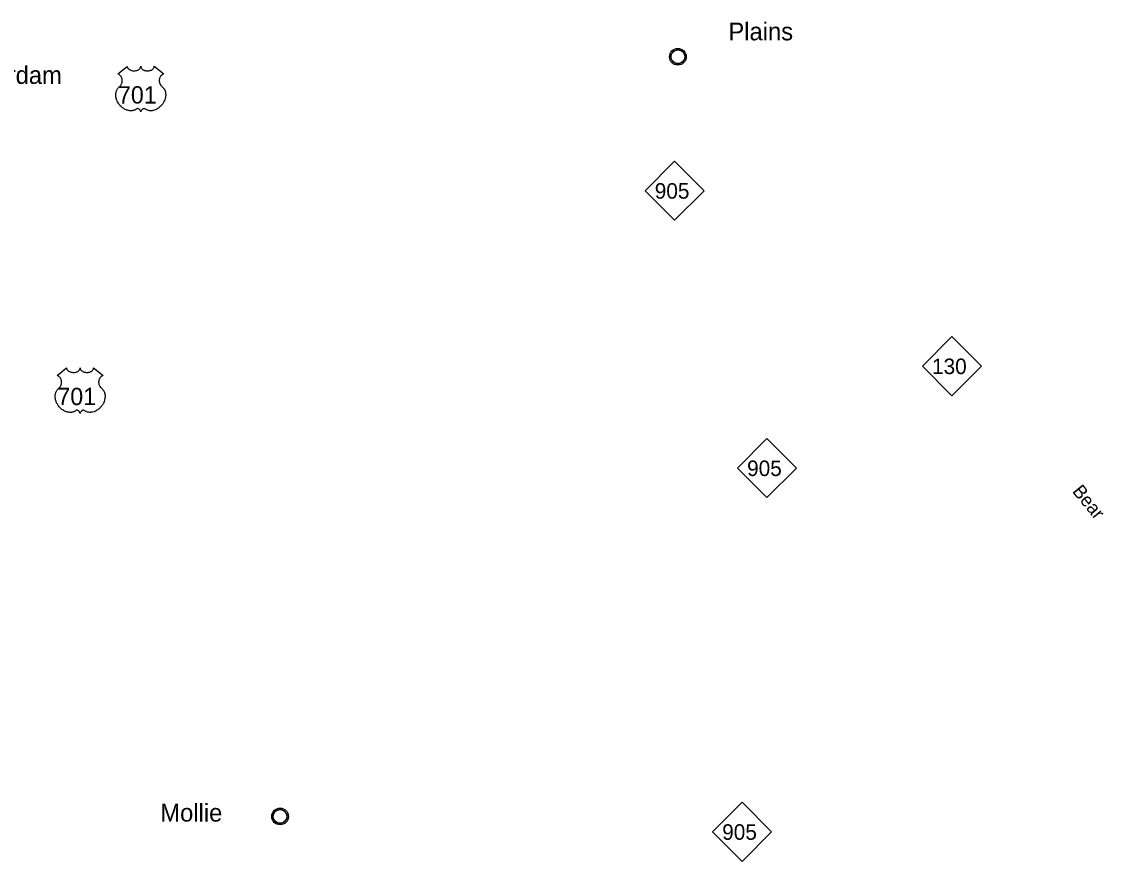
# Model space of a CAD drawing. Extents: x 5197761 to 5514561, y 1890130 to 2080942.
# Drawn here: x 5297901 to 5346637, y 1945242 to 1983085 of the extents above; entities that cross this region are included whole.
import ezdxf

# ---------------------------------------------------------------- set-up
doc = ezdxf.new("R2010")
doc.units = 0
for name, color, linetype in [('Exist Civil Demographics Community CELL', 7, 'Continuous'), ('Exist Civil Demographics Community Label', 7, 'Continuous'), ('Exist Hydrographic Creek Single Shore Label', 7, 'Continuous'), ('Exist Road Primary NC Shield CELL', 7, 'Continuous'), ('Exist Road Primary NC Shield Number Label', 7, 'Continuous'), ('Exist Road Primary US Shield CELL', 7, 'Continuous'), ('Exist Road Primary US Shield Number Label', 7, 'Continuous')]:
    doc.layers.add(name, color=color, linetype=linetype)

msp = doc.modelspace()

# ---------------------------------------------------------------- linework, layer by layer
at = {"layer": 'Exist Civil Demographics Community CELL'}
for points in [[(5327158, 1981552), (5327162, 1981574), (5327169, 1981600), (5327180, 1981629), (5327192, 1981652), (5327205, 1981675), (5327220, 1981695), (5327236, 1981713), (5327255, 1981731), (5327277, 1981750), (5327299, 1981764), (5327318, 1981776), (5327338, 1981786), (5327360, 1981795), (5327383, 1981802), (5327400, 1981807), (5327419, 1981810), (5327436, 1981813), (5327461, 1981814), (5327479, 1981813), (5327502, 1981812), (5327521, 1981809), (5327541, 1981805), (5327561, 1981800), (5327582, 1981792), (5327608, 1981780), (5327633, 1981766), (5327654, 1981752), (5327674, 1981736), (5327687, 1981723), (5327704, 1981706), (5327719, 1981687), (5327732, 1981669), (5327744, 1981649), (5327754, 1981628), (5327762, 1981608), (5327768, 1981588), (5327774, 1981570), (5327778, 1981545), (5327780, 1981527), (5327781, 1981503), (5327781, 1981479), (5327778, 1981457), (5327775, 1981435), (5327768, 1981410), (5327761, 1981387), (5327751, 1981366), (5327739, 1981342), (5327726, 1981321), (5327712, 1981302), (5327695, 1981283), (5327674, 1981264), (5327654, 1981247), (5327634, 1981233), (5327616, 1981223), (5327589, 1981210), (5327561, 1981200), (5327537, 1981194), (5327510, 1981188), (5327493, 1981187), (5327475, 1981186), (5327452, 1981186), (5327435, 1981187), (5327413, 1981190), (5327389, 1981195), (5327371, 1981201), (5327350, 1981208), (5327332, 1981216), (5327316, 1981225), (5327289, 1981241), (5327266, 1981258), (5327247, 1981276), (5327229, 1981296), (5327216, 1981312), (5327204, 1981328), (5327188, 1981357), (5327181, 1981371), (5327174, 1981387), (5327164, 1981420), (5327158, 1981448), (5327155, 1981469), (5327154, 1981494), (5327153, 1981513), (5327156, 1981538)], [(5309233, 1947316), (5309237, 1947338), (5309244, 1947364), (5309256, 1947393), (5309267, 1947416), (5309281, 1947439), (5309296, 1947459), (5309312, 1947477), (5309330, 1947495), (5309352, 1947514), (5309374, 1947528), (5309393, 1947540), (5309414, 1947550), (5309436, 1947559), (5309458, 1947566), (5309475, 1947571), (5309495, 1947574), (5309511, 1947577), (5309537, 1947578), (5309554, 1947577), (5309577, 1947576), (5309597, 1947573), (5309616, 1947569), (5309636, 1947564), (5309657, 1947556), (5309684, 1947544), (5309709, 1947530), (5309729, 1947516), (5309750, 1947500), (5309763, 1947487), (5309779, 1947470), (5309795, 1947451), (5309807, 1947433), (5309820, 1947413), (5309829, 1947392), (5309838, 1947372), (5309844, 1947352), (5309849, 1947334), (5309853, 1947309), (5309856, 1947291), (5309857, 1947267), (5309856, 1947243), (5309854, 1947221), (5309850, 1947199), (5309844, 1947174), (5309836, 1947151), (5309827, 1947131), (5309814, 1947107), (5309801, 1947085), (5309787, 1947066), (5309770, 1947047), (5309749, 1947028), (5309729, 1947011), (5309709, 1946997), (5309692, 1946987), (5309665, 1946974), (5309636, 1946964), (5309612, 1946958), (5309586, 1946953), (5309568, 1946951), (5309550, 1946950), (5309528, 1946950), (5309511, 1946951), (5309488, 1946954), (5309464, 1946959), (5309446, 1946965), (5309425, 1946972), (5309407, 1946980), (5309391, 1946989), (5309364, 1947005), (5309342, 1947022), (5309322, 1947040), (5309304, 1947060), (5309292, 1947076), (5309280, 1947092), (5309263, 1947121), (5309256, 1947135), (5309250, 1947151), (5309239, 1947184), (5309233, 1947212), (5309230, 1947233), (5309229, 1947258), (5309229, 1947277), (5309231, 1947303)]]:
    msp.add_lwpolyline(points, close=True, dxfattribs=at)
for centre, radius in [((5327468, 1981502), 377), ((5327467, 1981503), 307), ((5309544, 1947266), 377), ((5309542, 1947267), 307)]:
    msp.add_circle(centre, radius, dxfattribs=at)
at = {"layer": 'Exist Road Primary NC Shield CELL'}
for points in [[(5325990, 1975466), (5327322, 1976798), (5328654, 1975466), (5327322, 1974134)], [(5338481, 1967560), (5339813, 1968892), (5341145, 1967560), (5339813, 1966228)], [(5330150, 1962966), (5331482, 1964298), (5332814, 1962966), (5331482, 1961634)], [(5329028, 1946574), (5330360, 1947906), (5331692, 1946574), (5330360, 1945242)]]:
    msp.add_lwpolyline(points, close=True, dxfattribs=at)
at = {"layer": 'Exist Road Primary US Shield CELL'}
for points in [[(5302659, 1981070), (5302660, 1981053), (5302664, 1981032), (5302667, 1981021), (5302677, 1981000), (5302693, 1980976), (5302716, 1980952), (5302741, 1980931), (5302758, 1980920), (5302787, 1980905), (5302820, 1980891), (5302857, 1980880), (5302894, 1980873), (5302935, 1980868), (5302975, 1980867), (5303019, 1980871), (5303067, 1980880), (5303090, 1980886), (5303114, 1980894), (5303137, 1980904), (5303163, 1980917), (5303183, 1980931), (5303199, 1980942), (5303222, 1980964), (5303240, 1980986), (5303247, 1980999), (5303254, 1981011), (5303263, 1981036), (5303265, 1981048), (5303267, 1981071), (5303268, 1981051), (5303270, 1981039), (5303274, 1981027), (5303279, 1981014), (5303288, 1980996), (5303298, 1980981), (5303317, 1980959), (5303329, 1980948), (5303339, 1980939), (5303368, 1980919), (5303402, 1980902), (5303419, 1980895), (5303436, 1980889), (5303457, 1980882), (5303480, 1980877), (5303502, 1980873), (5303524, 1980870), (5303547, 1980868), (5303566, 1980867), (5303589, 1980868), (5303611, 1980869), (5303632, 1980872), (5303657, 1980876), (5303676, 1980880), (5303701, 1980887), (5303725, 1980895), (5303745, 1980904), (5303771, 1980917), (5303793, 1980931), (5303808, 1980943), (5303827, 1980960), (5303844, 1980981), (5303855, 1980996), (5303862, 1981011), (5303869, 1981027), (5303873, 1981044), (5303875, 1981059), (5303875, 1981072), (5304300, 1980733), (5304290, 1980729), (5304267, 1980718), (5304249, 1980707), (5304220, 1980686), (5304207, 1980675), (5304195, 1980663), (5304183, 1980651), (5304173, 1980639), (5304161, 1980622), (5304150, 1980605), (5304139, 1980586), (5304131, 1980570), (5304118, 1980535), (5304111, 1980514), (5304107, 1980495), (5304102, 1980458), (5304101, 1980439), (5304101, 1980422), (5304102, 1980403), (5304104, 1980385), (5304107, 1980366), (5304110, 1980349), (5304116, 1980329), (5304123, 1980305), (5304132, 1980282), (5304152, 1980246), (5304177, 1980208), (5304195, 1980187), (5304212, 1980169), (5304238, 1980147), (5304253, 1980134), (5304269, 1980118), (5304296, 1980087), (5304306, 1980072), (5304317, 1980056), (5304327, 1980039), (5304337, 1980021), (5304345, 1980005), (5304360, 1979969), (5304371, 1979933), (5304376, 1979915), (5304384, 1979873), (5304387, 1979852), (5304390, 1979812), (5304391, 1979762), (5304387, 1979716), (5304378, 1979661), (5304371, 1979629), (5304360, 1979591), (5304349, 1979558), (5304329, 1979509), (5304312, 1979474), (5304290, 1979433), (5304274, 1979408), (5304257, 1979381), (5304234, 1979351), (5304208, 1979318), (5304177, 1979284), (5304151, 1979258), (5304118, 1979229), (5304098, 1979212), (5304070, 1979191), (5304030, 1979164), (5303992, 1979142), (5303959, 1979125), (5303930, 1979113), (5303892, 1979098), (5303829, 1979081), (5303806, 1979076), (5303779, 1979072), (5303754, 1979070), (5303729, 1979068), (5303696, 1979068), (5303663, 1979071), (5303632, 1979075), (5303600, 1979082), (5303566, 1979092), (5303535, 1979104), (5303504, 1979119), (5303451, 1979153), (5303436, 1979161), (5303428, 1979163), (5303407, 1979164), (5303388, 1979160), (5303369, 1979152), (5303357, 1979146), (5303341, 1979135), (5303329, 1979126), (5303315, 1979112), (5303305, 1979101), (5303297, 1979092), (5303282, 1979068), (5303277, 1979057), (5303271, 1979043), (5303266, 1979022), (5303260, 1979048), (5303252, 1979066), (5303243, 1979081), (5303234, 1979094), (5303219, 1979111), (5303205, 1979124), (5303189, 1979137), (5303172, 1979148), (5303159, 1979155), (5303146, 1979159), (5303131, 1979163), (5303118, 1979164), (5303108, 1979164), (5303094, 1979161), (5303074, 1979147), (5303056, 1979134), (5303036, 1979122), (5303013, 1979109), (5302996, 1979101), (5302975, 1979093), (5302951, 1979085), (5302925, 1979078), (5302898, 1979073), (5302874, 1979069), (5302849, 1979067), (5302826, 1979066), (5302802, 1979067), (5302780, 1979068), (5302754, 1979071), (5302722, 1979075), (5302695, 1979081), (5302667, 1979089), (5302638, 1979098), (5302607, 1979110), (5302569, 1979127), (5302542, 1979141), (5302499, 1979165), (5302450, 1979199), (5302412, 1979230), (5302385, 1979255), (5302344, 1979296), (5302321, 1979323), (5302283, 1979371), (5302259, 1979406), (5302244, 1979431), (5302221, 1979473), (5302209, 1979498), (5302193, 1979536), (5302180, 1979571), (5302170, 1979603), (5302164, 1979624), (5302156, 1979660), (5302151, 1979686), (5302146, 1979722), (5302144, 1979759), (5302143, 1979794), (5302144, 1979822), (5302147, 1979856), (5302153, 1979891), (5302160, 1979921), (5302166, 1979943), (5302175, 1979970), (5302187, 1979999), (5302201, 1980027), (5302214, 1980051), (5302231, 1980076), (5302248, 1980097), (5302269, 1980121), (5302292, 1980143), (5302313, 1980159), (5302337, 1980183), (5302350, 1980198), (5302366, 1980218), (5302378, 1980237), (5302388, 1980254), (5302401, 1980279), (5302408, 1980298), (5302418, 1980326), (5302423, 1980346), (5302428, 1980372), (5302431, 1980396), (5302433, 1980427), (5302432, 1980452), (5302429, 1980481), (5302423, 1980510), (5302416, 1980534), (5302406, 1980562), (5302396, 1980583), (5302380, 1980611), (5302362, 1980637), (5302343, 1980658), (5302324, 1980677), (5302306, 1980691), (5302289, 1980703), (5302267, 1980716), (5302247, 1980726), (5302233, 1980732)], [(5299928, 1967478), (5299929, 1967461), (5299934, 1967440), (5299937, 1967429), (5299947, 1967408), (5299963, 1967384), (5299985, 1967360), (5300011, 1967339), (5300028, 1967328), (5300057, 1967313), (5300090, 1967299), (5300126, 1967288), (5300164, 1967281), (5300205, 1967276), (5300245, 1967275), (5300289, 1967279), (5300337, 1967288), (5300359, 1967294), (5300384, 1967302), (5300407, 1967312), (5300432, 1967325), (5300453, 1967338), (5300469, 1967350), (5300491, 1967372), (5300509, 1967394), (5300517, 1967407), (5300523, 1967419), (5300532, 1967444), (5300535, 1967455), (5300537, 1967479), (5300538, 1967459), (5300540, 1967447), (5300543, 1967435), (5300548, 1967422), (5300557, 1967404), (5300567, 1967389), (5300586, 1967367), (5300598, 1967356), (5300609, 1967347), (5300638, 1967327), (5300672, 1967310), (5300688, 1967303), (5300705, 1967296), (5300727, 1967290), (5300749, 1967285), (5300771, 1967281), (5300794, 1967278), (5300817, 1967276), (5300836, 1967275), (5300859, 1967276), (5300880, 1967277), (5300902, 1967279), (5300926, 1967283), (5300946, 1967288), (5300971, 1967294), (5300994, 1967303), (5301015, 1967312), (5301041, 1967325), (5301062, 1967339), (5301078, 1967351), (5301096, 1967368), (5301114, 1967389), (5301124, 1967403), (5301132, 1967419), (5301138, 1967435), (5301143, 1967452), (5301145, 1967467), (5301145, 1967479), (5301570, 1967141), (5301560, 1967137), (5301537, 1967126), (5301519, 1967115), (5301489, 1967094), (5301477, 1967083), (5301464, 1967071), (5301453, 1967059), (5301443, 1967047), (5301430, 1967030), (5301419, 1967013), (5301408, 1966994), (5301400, 1966977), (5301387, 1966943), (5301381, 1966922), (5301377, 1966903), (5301372, 1966865), (5301371, 1966847), (5301371, 1966829), (5301372, 1966811), (5301374, 1966793), (5301377, 1966774), (5301380, 1966757), (5301385, 1966737), (5301393, 1966713), (5301402, 1966690), (5301421, 1966653), (5301446, 1966616), (5301464, 1966595), (5301482, 1966577), (5301508, 1966554), (5301522, 1966542), (5301539, 1966526), (5301565, 1966495), (5301576, 1966480), (5301587, 1966464), (5301597, 1966447), (5301607, 1966429), (5301615, 1966413), (5301630, 1966377), (5301641, 1966341), (5301646, 1966323), (5301654, 1966281), (5301657, 1966260), (5301660, 1966220), (5301660, 1966170), (5301656, 1966124), (5301648, 1966069), (5301640, 1966036), (5301629, 1965999), (5301618, 1965966), (5301599, 1965917), (5301582, 1965882), (5301559, 1965841), (5301544, 1965816), (5301526, 1965789), (5301504, 1965759), (5301478, 1965726), (5301446, 1965692), (5301421, 1965666), (5301388, 1965637), (5301368, 1965620), (5301339, 1965598), (5301300, 1965572), (5301261, 1965550), (5301229, 1965533), (5301199, 1965521), (5301162, 1965506), (5301099, 1965489), (5301076, 1965484), (5301049, 1965480), (5301024, 1965478), (5300999, 1965476), (5300966, 1965476), (5300933, 1965479), (5300902, 1965483), (5300869, 1965490), (5300836, 1965500), (5300805, 1965512), (5300774, 1965527), (5300721, 1965560), (5300706, 1965568), (5300697, 1965571), (5300677, 1965572), (5300658, 1965568), (5300638, 1965560), (5300627, 1965554), (5300611, 1965543), (5300599, 1965534), (5300584, 1965520), (5300574, 1965508), (5300567, 1965499), (5300552, 1965476), (5300546, 1965465), (5300541, 1965451), (5300536, 1965430), (5300529, 1965456), (5300522, 1965474), (5300513, 1965489), (5300503, 1965502), (5300488, 1965519), (5300475, 1965532), (5300459, 1965545), (5300442, 1965555), (5300428, 1965562), (5300416, 1965567), (5300400, 1965571), (5300388, 1965572), (5300378, 1965572), (5300363, 1965569), (5300344, 1965555), (5300326, 1965542), (5300306, 1965530), (5300282, 1965517), (5300265, 1965509), (5300245, 1965501), (5300220, 1965493), (5300194, 1965486), (5300167, 1965481), (5300144, 1965477), (5300119, 1965475), (5300096, 1965474), (5300072, 1965475), (5300050, 1965476), (5300024, 1965479), (5299992, 1965483), (5299965, 1965489), (5299937, 1965497), (5299908, 1965506), (5299877, 1965518), (5299838, 1965535), (5299811, 1965548), (5299769, 1965573), (5299719, 1965607), (5299682, 1965638), (5299654, 1965662), (5299614, 1965704), (5299590, 1965731), (5299553, 1965779), (5299529, 1965814), (5299514, 1965839), (5299491, 1965880), (5299479, 1965906), (5299463, 1965944), (5299450, 1965978), (5299439, 1966011), (5299434, 1966032), (5299426, 1966068), (5299421, 1966094), (5299416, 1966130), (5299413, 1966167), (5299413, 1966201), (5299414, 1966230), (5299417, 1966264), (5299423, 1966299), (5299429, 1966329), (5299436, 1966351), (5299445, 1966378), (5299456, 1966407), (5299471, 1966435), (5299484, 1966459), (5299501, 1966484), (5299517, 1966505), (5299539, 1966529), (5299562, 1966550), (5299582, 1966567), (5299607, 1966591), (5299620, 1966606), (5299635, 1966626), (5299648, 1966645), (5299657, 1966662), (5299670, 1966687), (5299678, 1966705), (5299688, 1966734), (5299693, 1966754), (5299698, 1966780), (5299701, 1966804), (5299702, 1966835), (5299702, 1966860), (5299698, 1966889), (5299693, 1966917), (5299686, 1966942), (5299676, 1966970), (5299666, 1966991), (5299650, 1967019), (5299631, 1967045), (5299613, 1967066), (5299594, 1967084), (5299576, 1967099), (5299559, 1967111), (5299537, 1967124), (5299516, 1967134), (5299503, 1967139)]]:
    msp.add_lwpolyline(points, close=True, dxfattribs=at)

# ---------------------------------------------------------------- texts
at = {"layer": 'Exist Civil Demographics Community Label'}
for s, p in [('Plains', (5329743, 1982242)), ('Beaverdam', (5294241, 1980278)), ('Mollie', (5304148, 1947035))]:
    msp.add_text(s, height=800, dxfattribs=at).set_placement(p)
at = {"layer": 'Exist Hydrographic Creek Single Shore Label'}
msp.add_text('Bear', height=600, rotation=309.4852, dxfattribs=at).set_placement((5345209, 1961906))
at = {"layer": 'Exist Road Primary NC Shield Number Label'}
for s, p in [('905', (5326426, 1975107)), ('130', (5338918, 1967201)), ('905', (5330586, 1962607)), ('905', (5329464, 1946215))]:
    msp.add_text(s, height=700, dxfattribs=at).set_placement(p)
at = {"layer": 'Exist Road Primary US Shield Number Label'}
for p in [(5302243, 1979395), (5299513, 1965803)]:
    msp.add_text('701', height=780, dxfattribs=at).set_placement(p)

doc.saveas('drawing.dxf')
